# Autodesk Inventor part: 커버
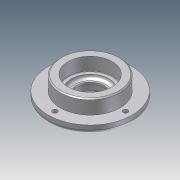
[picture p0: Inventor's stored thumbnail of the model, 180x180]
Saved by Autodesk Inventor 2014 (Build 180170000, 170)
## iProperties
Company: 한국ATC센터
Created: 2014-10
Part Number: 커버
Document SubType Name: Modeling
Designer: KYOUNG IL JANG
Density: 7.85 g/cm^3
Mass: 44.7286 g
Surface Area: 161.165 cm^2
Volume: 44.7286 cm^3
Material: 강철
Appearance: 강철
Author: KYOUNG IL JANG
Revision Number: 1
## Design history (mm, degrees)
sketch "스케치1"
  geometry: C1 r 38 at (0, 0); 1 further point
  constraints: 1 centre point, 1 coincident
  dimensions: "d0" = 76 diameter of C1
extrude "돌출1" new body sketch "스케치1" distance "d1" = 7; taper "d2" = 0 deg
sketch "스케치2"
  geometry: C1 r 27 at (0, 0); 1 further point
  constraints: 1 centre point, 1 coincident
  dimensions: "d3" = 54 diameter of C1
extrude "돌출2" join sketch "스케치2" distance "d4" = 13; taper "d5" = 0 deg
sketch "스케치3"
  geometry: C1 r 20 at (0, 0); 1 further point
  constraints: 1 centre point, 1 coincident
  dimensions: "d6" = 40 diameter of C1
extrude "돌출3" join sketch "스케치3" distance "d7" = 5; taper "d8" = 0 deg
hole "구멍1" diameter "d11" = 25; stored, may be unused: countersink angle "d15" = 90 deg, drill point angle "d17" = 118 deg; dims "d9" = 10, "d10" = 10, "d12" = 6, "d13" = 32, "d14" = 8.3, "d16" = 8
hole "구멍2" diameter "d20" = 34; stored, may be unused: countersink angle "d24" = 90 deg, drill point angle "d26" = 0 deg; dims "d18" = 10, "d19" = 10, "d21" = 6, "d22" = 40, "d23" = 12, "d25" = 3
fillet "모깎기2" dims "d34" = 3
fillet "모깎기1" dims "d27" = 0.3
chamfer "모따기1" distance "d28" = 1; stored, may be unused: second distance "d29" = 2, angle "d30" = 45 deg
chamfer "모따기2" distance "d31" = 1.2; stored, may be unused: second distance "d32" = 2, angle "d33" = 30 deg
sketch "스케치4" dims "d35" = 64
  geometry: 3 further points
  constraints: 2 horizontal alignment, 1 coincident, 2 other
hole "구멍3" sketch "스케치4" at (32, 0) diameter "d36" = 4.5; stored, may be unused: countersink angle "d40" = 90 deg, drill point angle "d42" = 118 deg; dims "d37" = 6, "d38" = 8, "d39" = 4.4, "d41" = 13
node "솔리드1"
pattern_circular "원형 패턴1" dims angle "d44" = 360 deg
